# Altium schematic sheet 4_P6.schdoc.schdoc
size 309 x 223 mm; Symbol: A4_Schematic_0605; Device: A4_Schematic_0605; @Project Name: MDIO-Board_Rev_01(0124); @Page Count: 10; @Update Date: 2024-05-21; @Create Date: 2024-05-19; @Schematic Name: Schematic1; @Page No: 6; @Page Name: P6
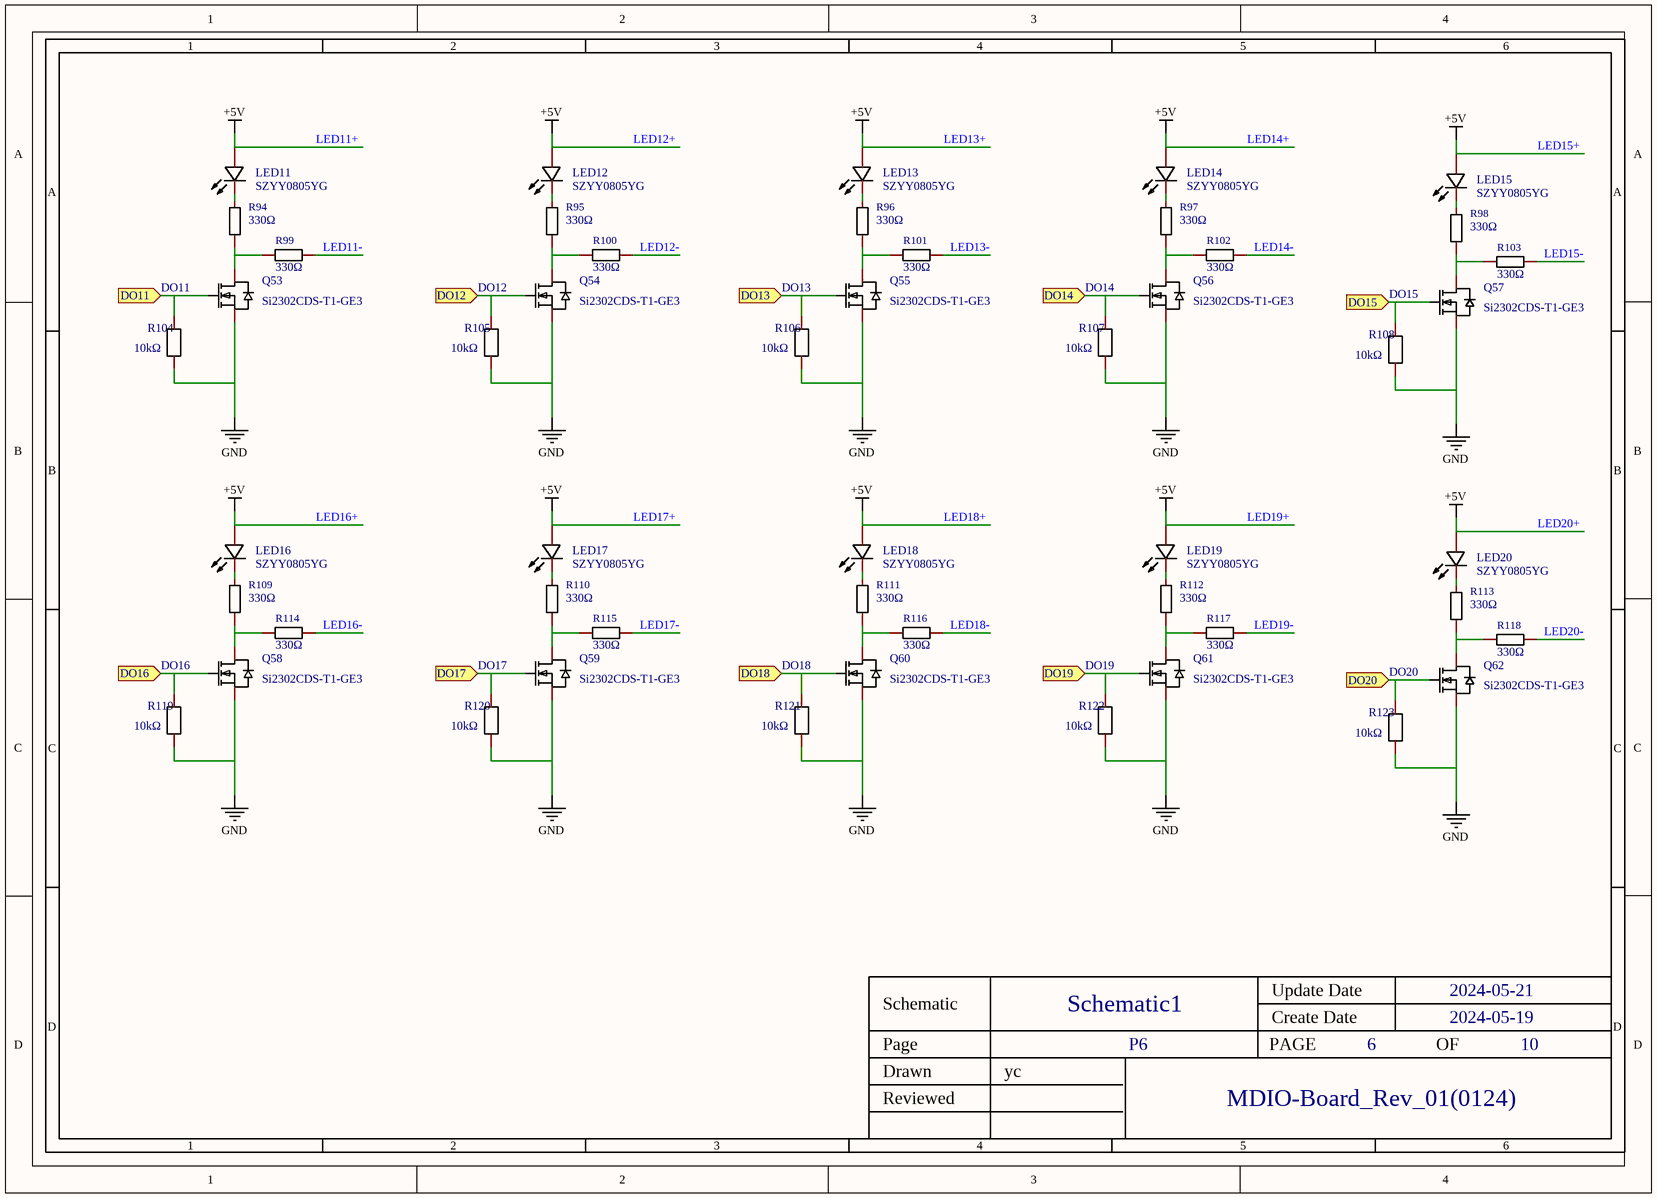
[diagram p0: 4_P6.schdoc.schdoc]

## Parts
LED11  SZYY0805YG  [LED0805-R-RD_GREEN]
LED12  SZYY0805YG  [LED0805-R-RD_GREEN]
LED13  SZYY0805YG  [LED0805-R-RD_GREEN]
LED14  SZYY0805YG  [LED0805-R-RD_GREEN]
LED15  SZYY0805YG  [LED0805-R-RD_GREEN]
LED16  SZYY0805YG  [LED0805-R-RD_GREEN]
LED17  SZYY0805YG  [LED0805-R-RD_GREEN]
LED18  SZYY0805YG  [LED0805-R-RD_GREEN]
LED19  SZYY0805YG  [LED0805-R-RD_GREEN]
LED20  SZYY0805YG  [LED0805-R-RD_GREEN]
Q53  Si2302CDS-T1-GE3  [SOT-23_L2.9-W1.3-P1.90-LS2.4-BR]
Q54  Si2302CDS-T1-GE3  [SOT-23_L2.9-W1.3-P1.90-LS2.4-BR]
Q55  Si2302CDS-T1-GE3  [SOT-23_L2.9-W1.3-P1.90-LS2.4-BR]
Q56  Si2302CDS-T1-GE3  [SOT-23_L2.9-W1.3-P1.90-LS2.4-BR]
Q57  Si2302CDS-T1-GE3  [SOT-23_L2.9-W1.3-P1.90-LS2.4-BR]
Q58  Si2302CDS-T1-GE3  [SOT-23_L2.9-W1.3-P1.90-LS2.4-BR]
Q59  Si2302CDS-T1-GE3  [SOT-23_L2.9-W1.3-P1.90-LS2.4-BR]
Q60  Si2302CDS-T1-GE3  [SOT-23_L2.9-W1.3-P1.90-LS2.4-BR]
Q61  Si2302CDS-T1-GE3  [SOT-23_L2.9-W1.3-P1.90-LS2.4-BR]
Q62  Si2302CDS-T1-GE3  [SOT-23_L2.9-W1.3-P1.90-LS2.4-BR]
R94  330Ω  [R0603]
R95  330Ω  [R0603]
R96  330Ω  [R0603]
R97  330Ω  [R0603]
R98  330Ω  [R0603]
R99  330Ω  [R0603]
R100  330Ω  [R0603]
R101  330Ω  [R0603]
R102  330Ω  [R0603]
R103  330Ω  [R0603]
R104  10kΩ  [R0603]
R105  10kΩ  [R0603]
R106  10kΩ  [R0603]
R107  10kΩ  [R0603]
R108  10kΩ  [R0603]
R109  330Ω  [R0603]
R110  330Ω  [R0603]
R111  330Ω  [R0603]
R112  330Ω  [R0603]
R113  330Ω  [R0603]
R114  330Ω  [R0603]
R115  330Ω  [R0603]
R116  330Ω  [R0603]
R117  330Ω  [R0603]
R118  330Ω  [R0603]
R119  10kΩ  [R0603]
R120  10kΩ  [R0603]
R121  10kΩ  [R0603]
R122  10kΩ  [R0603]
R123  10kΩ  [R0603]

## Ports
DO11 (in), DO12 (in), DO13 (in), DO14 (in), DO15 (in), DO16 (in), DO17 (in), DO18 (in), DO19 (in), DO20 (in)

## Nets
GND: Q53.2(S) Q54.2(S) Q55.2(S) Q56.2(S) Q57.2(S) Q58.2(S) Q59.2(S) Q60.2(S) Q61.2(S) Q62.2(S) R104.1 R105.1 R106.1 R107.1 R108.1 R119.1 R120.1 R121.1 R122.1 R123.1
LED11+: LED11.1(+) LED12.1(+) LED13.1(+) LED14.1(+) LED15.1(+) LED16.1(+) LED17.1(+) LED18.1(+) LED19.1(+) LED20.1(+)  [also labelled +5V, LED12+, LED13+, LED14+, LED15+, LED16+, LED17+, LED18+, LED19+, LED20+]
DO11: Q53.1(G) R104.2 ; port DO11
DO12: Q54.1(G) R105.2 ; port DO12
DO13: Q55.1(G) R106.2 ; port DO13
DO14: Q56.1(G) R107.2 ; port DO14
DO15: Q57.1(G) R108.2 ; port DO15
DO16: Q58.1(G) R119.2 ; port DO16
DO17: Q59.1(G) R120.2 ; port DO17
DO18: Q60.1(G) R121.2 ; port DO18
DO19: Q61.1(G) R122.2 ; port DO19
DO20: Q62.1(G) R123.2 ; port DO20
LED11-: R99.1
LED12-: R100.1
LED13-: R101.1
LED14-: R102.1
LED15-: R103.1
LED16-: R114.1
LED17-: R115.1
LED18-: R116.1
LED19-: R117.1
LED20-: R118.1
NetLED11_2: LED11.2(-) R94.2
NetLED12_2: LED12.2(-) R95.2
NetLED13_2: LED13.2(-) R96.2
NetLED14_2: LED14.2(-) R97.2
NetLED15_2: LED15.2(-) R98.2
NetLED16_2: LED16.2(-) R109.2
NetLED17_2: LED17.2(-) R110.2
NetLED18_2: LED18.2(-) R111.2
NetLED19_2: LED19.2(-) R112.2
NetLED20_2: LED20.2(-) R113.2
NetQ53_3: Q53.3(D) R94.1 R99.2
NetQ54_3: Q54.3(D) R95.1 R100.2
NetQ55_3: Q55.3(D) R96.1 R101.2
NetQ56_3: Q56.3(D) R97.1 R102.2
NetQ57_3: Q57.3(D) R98.1 R103.2
NetQ58_3: Q58.3(D) R109.1 R114.2
NetQ59_3: Q59.3(D) R110.1 R115.2
NetQ60_3: Q60.3(D) R111.1 R116.2
NetQ61_3: Q61.3(D) R112.1 R117.2
NetQ62_3: Q62.3(D) R113.1 R118.2

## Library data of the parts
LED11-LED20 = SZYY0805YG: Manufacturer: yongyu(永裕光电); Add into BOM: yes; Emitted Color: Green-yellow; Description: Emitted Color:Green-yellow
Q53-Q62 = Si2302CDS-T1-GE3: Manufacturer: VISHAY(威世); Add into BOM: yes; Type: 1个NChannel; Drain Source On Resistance (RDS(on)@Vgs,Id): 57mΩ@4.5V,3.6A; Gate Threshold Voltage (Vgs(th)@Id): 850mV@250uA; Total Gate Charge (Qg@Vgs): 5.5nC@4.5V; Description: Type:1个NChannel Drain Source Voltage (Vdss): Continuous Drain Current (Id): Power Dissipation (Pd): Drain Source On Resistance (RDS(on)@Vgs,Id):57mΩ@4.5V,3.6A Gate Threshold Voltage (Vgs(th)@Id):850mV@250uA Total Gate Charge (Qg@Vgs):5.5nC@4.5V Operating
R94-R103 R109-R118 = 0603WAF3300T5E: Manufacturer: UNI-ROYAL(厚声); Add into BOM: yes; Tolerance: ±1%; Temperature Coefficient: ±100ppm/℃; Description: Type:Thick Film Resistors Resistance: Tolerance:±1% Tolerance:±1% Power(Watts): Overload Voltage (Max): Temperature Coefficient:±100ppm/℃ Temperature Coefficient:±100ppm/℃ Operating Temperature Range:-55℃~+155℃ Operating Temperature Range:-55℃~+155℃
R104-R108 R119-R123 = SCR0603J10K: Manufacturer: VO(翔胜); Add into BOM: yes; Tolerance: ±5%; Description: Type:Thick Film Resistors Resistance: Tolerance:±5% Tolerance:±5% Power(Watts): Overload Voltage (Max): Operating Temperature Range:-55℃~+155℃ Operating Temperature Range:-55℃~+155℃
